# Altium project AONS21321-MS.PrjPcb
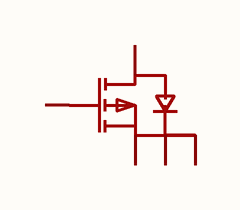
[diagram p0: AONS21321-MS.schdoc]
1 sheet, 1 parts. Net scope: global (net labels, ports and power ports of the same name join across sheets).

## Sheet AONS21321-MS.schdoc
size 127 x 101 mm

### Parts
Q?  aons21321-ms  [TDSON-8_L5.9-W5.2-P1.27-BL-1]  (value not drawn)

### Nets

Not connected (* = marked no-connect by the designer): Q? 1(S) 2(S) 3(S) 4(G) 5(D)

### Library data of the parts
Q? = aons21321-ms: 数量:1个P沟道;漏源电压(Vdss):30V;连续漏极电流(Id):50A;导通电阻(RDS(on)):9mΩ@10V;耗散功率(Pd):3W;阈值电压(Vgs(th)):1.5V;; Manufacturer: MSKSEMI(美森科); AddInBom: yes; ModelId: 6d3ef2b64d5a4f2dbd2ee02e0c7053d2; ModelTransform: 205.511,242.1255,0,0,0,0,0,42.913,0; Number: 1个P沟道; Drain to Source Voltage: 30V; Current - Continuous Drain(Id): 50A; Pd - Power Dissipation: 3W; Gate Threshold Voltage (Vgs(th)): 1.5V; Gate Charge(Qg): 24nC; Input Capacitance(Ciss): 1.75nF; Reverse Transfer Capacitance (Crss@Vds): 180pF; Configuration: 独立式; Type: P沟道; Output Capacitance(Coss): 215pF; Vgs: ±20V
